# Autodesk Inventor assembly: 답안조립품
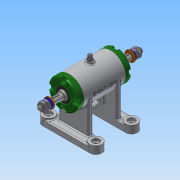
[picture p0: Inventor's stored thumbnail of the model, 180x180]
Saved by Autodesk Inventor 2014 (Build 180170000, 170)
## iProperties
Created: 2015-11
Part Number: 답안조립품
Document SubType Name: Assembly
Designer: 103-30
Author: 103-30
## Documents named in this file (15)
- C:\Users\103-30\Desktop\451110V1032\답안조립품.iam
- C:\Users\103-30\Desktop\451110V1032\1-본체.ipt
- C:\Users\103-30\Desktop\451110V1032\축.ipt
- C:\Users\103-30\Desktop\451110V1032\베어링 15 x 32 x 9.ipt
- C:\Users\103-30\Desktop\451110V1032\키 3 x 3 x 12.ipt
- C:\Users\103-30\Desktop\451110V1032\커버.ipt
- C:\Users\103-30\Desktop\451110V1032\오일 실 15 25 7.ipt
- C:\Users\103-30\Desktop\451110V1032\니플 M 6 x 0.75.ipt
- C:\Users\103-30\Desktop\451110V1032\스퍼기어.ipt
- C:\Users\103-30\Desktop\451110V1032\와셔 8x17.ipt
- C:\Users\103-30\Desktop\451110V1032\스프링와셔 8.ipt
- C:\Users\103-30\Desktop\451110V1032\너트 M 8.ipt
- C:\Users\103-30\Desktop\451110V1032\V벨트풀리.ipt
- C:\Users\103-30\Desktop\451110V1032\와셔 6x11.5.ipt
- C:\Users\103-30\Desktop\451110V1032\볼트 M 6 x 8.ipt
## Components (4 placed, 3 different names)
1. 1-본체:1
2. KS B 2023 6002 - 15 x 32 x 9:1
3. KS B 2023 6002 - 15 x 32 x 9:2
4. V벨트풀리:1 — 각도:4
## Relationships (1: Angle 1)
- 각도:4 [Angle]: V벨트풀리:1
## Named parameters: d12_d10 = 0, d13_d11 = 0
